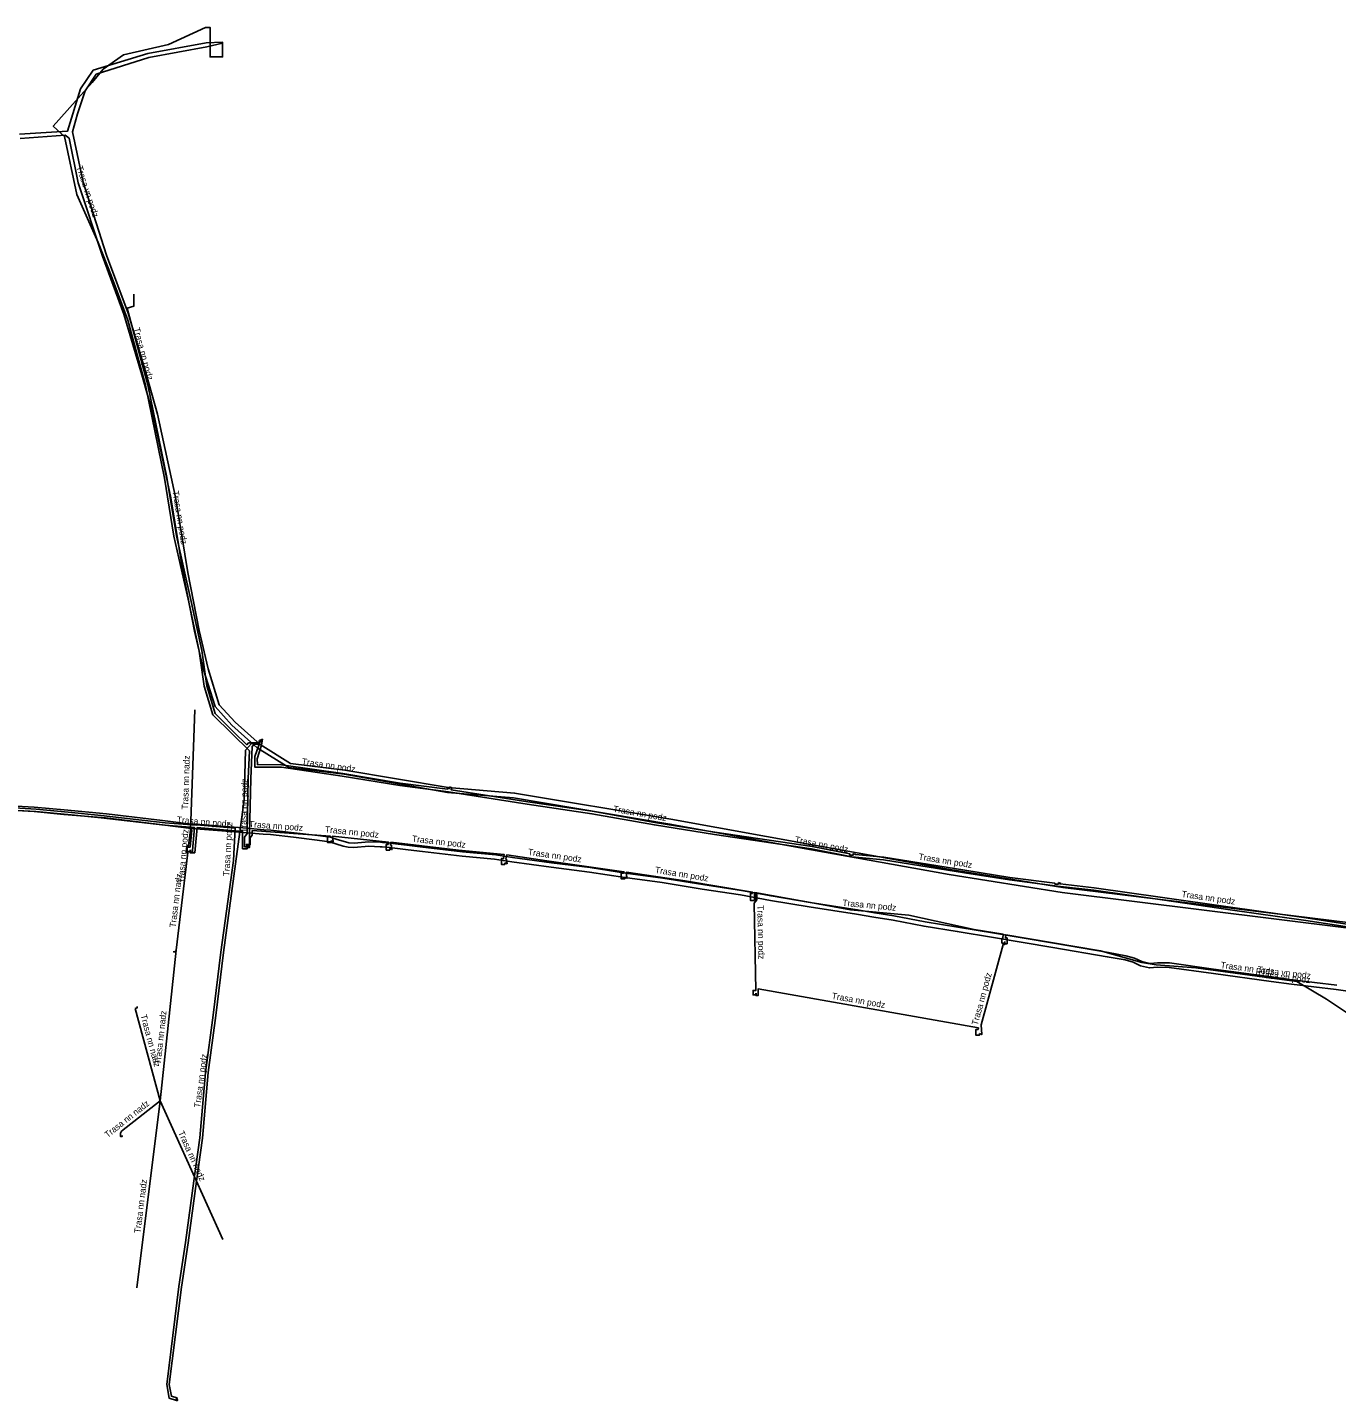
# Model space of a CAD drawing. Extents: x -704292 to -701313, y -1010090 to -1007885.
# Drawn here: x -702533.5 to -702326.6, y -1008863.3 to -1008646.4 of the extents above; entities that cross this region are included whole.
import ezdxf

# ---------------------------------------------------------------- set-up
doc = ezdxf.new("R2010")
doc.units = 0
for name, color, linetype in [('Level 13', 7, 'Continuous'), ('Level 15', 7, 'Continuous'), ('Level 20', 7, 'Continuous'), ('Level 25', 7, 'Continuous')]:
    doc.layers.add(name, color=color, linetype=linetype)

msp = doc.modelspace()

# ---------------------------------------------------------------- linework, layer by layer
at = {"layer": 'Level 13'}
for p, q in [((-702507.7, -1008773.21), (-702507.03, -1008754.23)), ((-702512.5, -1008815.97), (-702509.95, -1008792.21)), ((-702516.42, -1008801.39), (-702512.5, -1008815.97)), ((-702518.59, -1008820.78), (-702512.5, -1008815.97)), ((-702516.2, -1008845.55), (-702512.5, -1008815.97)), ((-702502.61, -1008837.9), (-702512.5, -1008815.97))]:
    msp.add_line(p, q, dxfattribs=at)
for points in [[(-702507.7, -1008773.21), (-702507.99, -1008775.67), (-702508.28, -1008775.71), (-702508.38, -1008776.75), (-702508.12, -1008776.76), (-702509.95, -1008792.21)], [(-702510.35, -1008792.35), (-702510.35, -1008792.46), (-702510.2, -1008792.46), (-702509.95, -1008792.21)], [(-702516.1, -1008801.09), (-702516.1, -1008801.29), (-702516.42, -1008801.39)], [(-702518.51, -1008821.47), (-702518.51, -1008821.64), (-702518.74, -1008821.64), (-702518.74, -1008821.11), (-702518.59, -1008820.78)]]:
    msp.add_lwpolyline(points, dxfattribs=at)
at = {"layer": 'Level 15'}
for points in [[(-702502.62, -1008648.89), (-702502.63, -1008651.08), (-702504.61, -1008651.08), (-702504.61, -1008646.43), (-702505.3, -1008646.44), (-702511.19, -1008649.13), (-702518.26, -1008650.73), (-702521.47, -1008653.04), (-702523.24, -1008655.1), (-702529.38, -1008662), (-702527.58, -1008663.66), (-702525.65, -1008672.8), (-702522.29, -1008680.39), (-702520.21, -1008685.61), (-702517.6, -1008692.67), (-702516.17, -1008697.91), (-702514.83, -1008702.96), (-702511.81, -1008717.61), (-702510.31, -1008726.81), (-702507.97, -1008737.19), (-702506.33, -1008744.93), (-702505.52, -1008750.49), (-702504.14, -1008755.01), (-702501.12, -1008758.01), (-702498.37, -1008760.72), (-702498.57, -1008765.08), (-702498.75, -1008773.77), (-702499.16, -1008774.32), (-702499.16, -1008775.86), (-702498.65, -1008775.86), (-702498.65, -1008775.66)], [(-702496.79, -1008759.05), (-702496.79, -1008759.45), (-702498.53, -1008759.45), (-702498.8, -1008759.74), (-702500.84, -1008757.73), (-702503.78, -1008754.79), (-702505.12, -1008750.41), (-702505.93, -1008744.85), (-702507.58, -1008737.11), (-702509.91, -1008726.73), (-702511.41, -1008717.53), (-702514.44, -1008702.86), (-702515.79, -1008697.81), (-702517.69, -1008690.79), (-702517.2, -1008690.63), (-702516.63, -1008690.44), (-702516.63, -1008688.55)], [(-702496.82, -1008759.05), (-702496.82, -1008759.55), (-702498.06, -1008759.55), (-702498.98, -1008760.59), (-702499.2, -1008768.46), (-702502.5, -1008792.58), (-702503.71, -1008802.52), (-702504.92, -1008811.53), (-702505.81, -1008821.88), (-702506.77, -1008828.66), (-702508.06, -1008838.41), (-702509.12, -1008845.4), (-702511.06, -1008860.78), (-702510.7, -1008862.65), (-702509.85, -1008862.91), (-702509.8, -1008863.07), (-702509.94, -1008863.07), (-702509.94, -1008863.33), (-702509.79, -1008863.33), (-702509.79, -1008863.19)], [(-702498.7, -1008775.66), (-702498.7, -1008775.96), (-702498.35, -1008775.96), (-702498.35, -1008773.75), (-702498.17, -1008765.1), (-702497.94, -1008759.99), (-702497.63, -1008759.65), (-702496.84, -1008759.65), (-702496.84, -1008759.05)], [(-702319.76, -1008789.31), (-702331.48, -1008787.48), (-702343.45, -1008785.8), (-702354.18, -1008784.26), (-702364.96, -1008782.73), (-702370.7, -1008782.08), (-702378.28, -1008781.1), (-702385.41, -1008779.96), (-702398.19, -1008777.9), (-702403.2, -1008777.43), (-702409.56, -1008776.2), (-702424.93, -1008773.93), (-702434.39, -1008772.4), (-702444.27, -1008770.65), (-702454.48, -1008769.15), (-702466.95, -1008767.2), (-702474.61, -1008766.2), (-702483.71, -1008764.69), (-702493.33, -1008763.3), (-702497.55, -1008763.27), (-702497.51, -1008761.6), (-702496.67, -1008759.25), (-702496.57, -1008759.25), (-702496.57, -1008759.08), (-702496.66, -1008759.01), (-702496.77, -1008758.98)], [(-702466.77, -1008766.37), (-702466.77, -1008766.63), (-702467.1, -1008766.63), (-702467.11, -1008766.77), (-702474.55, -1008765.8), (-702483.65, -1008764.29), (-702493.3, -1008762.9), (-702497.12, -1008762.87), (-702497.16, -1008761.96), (-702496.47, -1008759.83), (-702496.34, -1008758.88), (-702496.63, -1008759.04), (-702496.79, -1008758.98)], [(-702507.73, -1008776.34), (-702507.73, -1008776.71), (-702507.39, -1008776.71), (-702507.39, -1008776.44), (-702507.06, -1008772.82), (-702511.76, -1008772.45), (-702521.83, -1008771.29), (-702527.06, -1008770.78), (-702532.12, -1008770.3), (-702540.73, -1008769.79), (-702546.04, -1008769.42), (-702550.78, -1008769.18), (-702555.11, -1008768.84), (-702558.87, -1008768.34), (-702563, -1008767.7), (-702567.32, -1008767.51), (-702571.85, -1008767.18), (-702574.96, -1008766.8), (-702575.12, -1008767.62), (-702574.91, -1008767.62), (-702574.81, -1008768.33), (-702575.16, -1008768.17)], [(-702402.98, -1008776.91), (-702402.98, -1008777.17), (-702403.53, -1008777.17), (-702403.53, -1008776.96), (-702409.5, -1008775.8), (-702424.87, -1008773.53), (-702434.33, -1008772), (-702444.21, -1008770.25), (-702454.42, -1008768.75), (-702466.52, -1008766.86), (-702466.42, -1008766.53), (-702466.77, -1008766.37)], [(-702509.77, -1008863.19), (-702509.77, -1008863.31), (-702509.9, -1008863.31), (-702511.04, -1008862.96), (-702511.46, -1008860.8), (-702509.52, -1008845.34), (-702508.46, -1008838.35), (-702507.17, -1008828.6), (-702506.21, -1008821.84), (-702505.32, -1008811.49), (-702504.11, -1008802.46), (-702502.9, -1008792.52), (-702500.92, -1008778.02), (-702500.62, -1008772.89), (-702506.75, -1008772.41), (-702506.76, -1008772.44), (-702511.72, -1008772.05), (-702521.79, -1008770.89), (-702527.02, -1008770.38), (-702532.09, -1008769.9), (-702540.71, -1008769.39)], [(-702507.71, -1008776.34), (-702507.71, -1008776.61), (-702508.2, -1008776.61), (-702508.2, -1008775.9), (-702507.75, -1008775.9), (-702507.5, -1008773.21), (-702507.7, -1008773.21)], [(-702507.76, -1008776.34), (-702507.76, -1008776.81), (-702507.03, -1008776.81), (-702506.66, -1008772.82), (-702499.46, -1008773.44), (-702499.46, -1008776.17), (-702498.73, -1008776.17), (-702498.73, -1008775.66)], [(-702498.73, -1008775.59), (-702498.85, -1008775.63), (-702498.85, -1008775.48), (-702498.57, -1008775.48), (-702498.25, -1008775.51), (-702498.25, -1008774.44), (-702497.96, -1008774.04), (-702497.94, -1008773.29), (-702485.6, -1008774.18), (-702485.64, -1008774.27), (-702486.07, -1008774.27), (-702486.07, -1008775.18), (-702485.52, -1008775.18), (-702485.52, -1008774.92)], [(-702485.52, -1008774.92), (-702485.17, -1008775.08), (-702485.27, -1008774.2), (-702476.43, -1008775.11), (-702476.47, -1008775.48), (-702476.77, -1008775.48), (-702476.77, -1008776.39), (-702476.22, -1008776.39), (-702476.22, -1008776.13)], [(-702476.22, -1008776.13), (-702475.87, -1008776.29), (-702475.96, -1008775.58), (-702476.08, -1008775.58), (-702476.03, -1008775.15), (-702465.34, -1008776.41), (-702458.13, -1008777.08), (-702458.24, -1008777.73), (-702458.57, -1008777.73), (-702458.57, -1008778.64), (-702458.02, -1008778.64), (-702458.02, -1008778.38)], [(-702458.02, -1008778.38), (-702457.67, -1008778.54), (-702457.77, -1008777.83), (-702457.85, -1008777.83), (-702457.73, -1008777.13), (-702451.39, -1008778.07), (-702439.21, -1008779.81), (-702439.27, -1008780.01), (-702439.64, -1008780.01), (-702439.64, -1008780.92), (-702439.09, -1008780.92), (-702439.09, -1008780.66)], [(-702370.56, -1008781.5), (-702370.56, -1008781.76), (-702371.11, -1008781.76), (-702371.11, -1008781.62), (-702378.22, -1008780.7), (-702385.35, -1008779.56), (-702398.14, -1008777.5), (-702402.63, -1008777.07), (-702402.98, -1008776.91)], [(-702439.09, -1008780.66), (-702438.74, -1008780.82), (-702438.83, -1008780.11), (-702438.88, -1008780.11), (-702438.81, -1008779.87), (-702429.55, -1008781.26), (-702418.92, -1008783.02), (-702418.91, -1008783.22), (-702419.24, -1008783.22), (-702419.24, -1008784.33), (-702418.59, -1008784.33), (-702418.59, -1008783.97)], [(-702319.56, -1008788.57), (-702319.56, -1008788.83), (-702319.9, -1008788.83), (-702319.91, -1008788.88), (-702331.42, -1008787.08), (-702343.39, -1008785.4), (-702354.12, -1008783.86), (-702364.92, -1008782.33), (-702370.3, -1008781.73), (-702370.21, -1008781.66), (-702370.56, -1008781.5)], [(-702418.59, -1008783.86), (-702418.59, -1008783.32), (-702418.23, -1008783.32), (-702418.23, -1008784.23), (-702418.66, -1008784.78), (-702418.35, -1008798.54), (-702418.81, -1008798.54), (-702418.81, -1008799.25), (-702418.31, -1008799.25), (-702418.31, -1008798.98)], [(-702418.59, -1008783.97), (-702418.33, -1008784.16), (-702418.33, -1008783.42), (-702418.5, -1008783.42), (-702418.52, -1008783.09), (-702408.57, -1008784.89), (-702403.41, -1008785.8), (-702394.19, -1008786.68), (-702383.89, -1008788.91), (-702379.28, -1008789.68), (-702379.34, -1008790.36), (-702379.5, -1008790.36), (-702379.5, -1008791.07), (-702379.04, -1008791.07), (-702379.04, -1008790.8)], [(-702383.04, -1008805.37), (-702382.69, -1008805.53), (-702382.79, -1008803.99), (-702379.3, -1008791.27), (-702379.02, -1008791.27), (-702379.02, -1008790.8)], [(-702314.19, -1008812.88), (-702315.88, -1008818.28), (-702316.13, -1008818.54), (-702318.33, -1008817.99), (-702319.09, -1008816.79), (-702318.78, -1008807.55), (-702318.87, -1008806.1), (-702321.26, -1008804.56), (-702328.21, -1008799.91), (-702332.91, -1008797.14), (-702337.2, -1008796.54), (-702348.84, -1008794.98), (-702355.12, -1008794.5), (-702357.38, -1008794.12), (-702363.94, -1008792.3), (-702378.88, -1008789.74), (-702378.92, -1008790.26), (-702378.69, -1008790.26), (-702378.69, -1008791.17), (-702379.04, -1008791.17), (-702379.04, -1008790.8)], [(-702383.04, -1008805.37), (-702383.04, -1008805.63), (-702383.59, -1008805.63), (-702383.59, -1008804.72), (-702383.26, -1008804.72), (-702383.21, -1008804.48), (-702418.01, -1008798.32), (-702418.01, -1008799.35), (-702418.36, -1008799.35), (-702418.36, -1008798.98)]]:
    msp.add_lwpolyline(points, dxfattribs=at)
at = {"layer": 'Level 25'}
for points in [[(-702502.64, -1008648.8), (-702502.64, -1008648.74), (-702505.24, -1008648.86), (-702514.44, -1008650.56), (-702523.07, -1008653.18), (-702525.09, -1008656.13), (-702527.12, -1008662.8), (-702534.71, -1008663.31)], [(-702309, -1008789.77), (-702369.85, -1008782.28), (-702387.67, -1008779.42), (-702409.42, -1008775.53), (-702431.79, -1008771.5), (-702456.5, -1008767.38), (-702467, -1008766.49), (-702483.31, -1008763.73), (-702491.89, -1008762.71), (-702496.71, -1008759.68), (-702500.65, -1008756.17), (-702503.16, -1008753.41), (-702504.91, -1008747.76), (-702506.33, -1008741.71), (-702508.13, -1008732.51), (-702510.07, -1008720.64), (-702512.91, -1008707.51), (-702514.69, -1008701.13), (-702517.56, -1008691.56), (-702520.96, -1008682.4), (-702524.67, -1008670.85), (-702526.32, -1008662.93), (-702525.55, -1008660.05), (-702524.36, -1008656.43), (-702522.58, -1008653.82), (-702514.27, -1008651.18), (-702505.11, -1008649.48), (-702502.64, -1008648.93), (-702502.64, -1008648.86)], [(-702534.63, -1008663.99), (-702527.49, -1008663.44), (-702526.89, -1008663.92), (-702525.43, -1008671), (-702521.62, -1008682.58), (-702518.23, -1008691.73), (-702515.36, -1008701.28), (-702513.6, -1008707.63), (-702510.78, -1008720.73), (-702508.84, -1008732.59), (-702507.04, -1008741.82), (-702505.62, -1008747.9), (-702503.81, -1008753.72), (-702501.18, -1008756.62), (-702497.17, -1008760.2), (-702492.16, -1008763.35), (-702483.44, -1008764.4), (-702467.08, -1008767.26), (-702456.64, -1008768.15), (-702431.96, -1008772.28), (-702409.6, -1008776.32), (-702387.84, -1008780.22), (-702370, -1008783.09), (-702313.69, -1008790.08)], [(-702496.1, -1008773.16), (-702498.72, -1008772.92), (-702506.9, -1008772.3), (-702507.53, -1008772.26), (-702512.1, -1008771.69), (-702520.94, -1008770.63), (-702527.65, -1008770.03), (-702532.39, -1008769.58), (-702539.91, -1008769.16)], [(-702496.19, -1008773.85), (-702498.7, -1008773.63), (-702506.85, -1008773.02), (-702507.57, -1008772.97), (-702512.13, -1008772.39), (-702521.14, -1008771.31), (-702527.7, -1008770.74), (-702532.4, -1008770.28), (-702539.92, -1008769.86)], [(-702321.88, -1008799.11), (-702326.66, -1008798.4), (-702333.74, -1008797.58), (-702336.95, -1008797.12), (-702346.04, -1008795.9), (-702353.08, -1008794.9), (-702354.93, -1008794.88), (-702356.18, -1008794.98), (-702357.61, -1008794.66), (-702358.76, -1008794.09), (-702360.03, -1008793.74), (-702362.85, -1008793.24), (-702371.46, -1008791.75), (-702380.82, -1008790.2), (-702386.55, -1008789.23), (-702391.8, -1008788.42), (-702396.7, -1008787.46), (-702399.72, -1008787), (-702402.49, -1008786.51), (-702409.95, -1008785.33), (-702416.06, -1008784.34), (-702420.81, -1008783.46), (-702426.88, -1008782.53), (-702433.18, -1008781.51), (-702439.08, -1008780.71), (-702444.68, -1008779.85), (-702450.69, -1008779.07), (-702456.93, -1008778.24), (-702459.64, -1008777.83), (-702464.78, -1008777.36), (-702471.05, -1008776.61), (-702473.33, -1008776.32), (-702475.39, -1008776.07), (-702476.24, -1008775.97), (-702477.42, -1008775.86), (-702477.73, -1008775.84), (-702479.51, -1008775.77), (-702481.9, -1008775.98), (-702482.77, -1008775.94), (-702483.56, -1008775.74), (-702485.71, -1008775.05), (-702487.67, -1008774.79), (-702491.43, -1008774.35), (-702495.06, -1008773.94), (-702496.19, -1008773.85)], [(-702326.56, -1008797.71), (-702333.65, -1008796.88), (-702336.89, -1008796.41), (-702346.06, -1008795.19), (-702353.02, -1008794.21), (-702354.9, -1008794.19), (-702356.14, -1008794.29), (-702357.39, -1008794), (-702358.53, -1008793.43), (-702359.9, -1008793.06), (-702362.68, -1008792.56), (-702371.27, -1008791.06), (-702380.66, -1008789.51), (-702386.47, -1008788.54), (-702391.61, -1008787.73), (-702396.56, -1008786.78), (-702399.58, -1008786.3), (-702402.36, -1008785.81), (-702409.8, -1008784.65), (-702415.97, -1008783.63), (-702420.66, -1008782.78), (-702426.73, -1008781.84), (-702433.07, -1008780.81), (-702438.95, -1008780.01), (-702444.56, -1008779.15), (-702450.64, -1008778.37), (-702456.84, -1008777.53), (-702459.45, -1008777.15), (-702464.7, -1008776.67), (-702470.97, -1008775.93), (-702473.11, -1008775.64), (-702475.32, -1008775.37), (-702476.15, -1008775.27), (-702477.35, -1008775.16), (-702477.66, -1008775.14), (-702479.5, -1008775.06), (-702481.83, -1008775.26), (-702482.67, -1008775.23), (-702484.7, -1008774.63), (-702485.59, -1008774.36), (-702487.59, -1008774.1), (-702491.33, -1008773.65), (-702494.98, -1008773.25), (-702496.1, -1008773.16)]]:
    msp.add_lwpolyline(points, dxfattribs=at)

# ---------------------------------------------------------------- texts
at = {"layer": 'Level 20'}
for s, rotation, p in [('Trasa vn podz', 288.2343, (-702525.74, -1008668.47)), ('Trasa nn podz', 284.9672, (-702516.71, -1008693.98)), ('Trasa nn podz', 279.26, (-702510.55, -1008719.7)), ('Trasa nn nadz', 87.9658, (-702508.09, -1008769.99)), ('Trasa nn podz', 351.7863, (-702490.16, -1008762.85)), ('Trasa nn podz', 88.8065, (-702498.85, -1008773.65)), ('Trasa nn podz', 349.9557, (-702440.98, -1008770.32)), ('Trasa nn podz', 355.1128, (-702509.9, -1008772.04)), ('Trasa nn podz', 355.9053, (-702498.48, -1008772.75)), ('Trasa nn podz', 84.8045, (-702508.77, -1008781.63)), ('Trasa nn podz', 86.7464, (-702501.56, -1008780.54)), ('Trasa nn podz', 354.1411, (-702486.49, -1008773.57)), ('Trasa nn podz', 353.2964, (-702472.75, -1008775.04)), ('Trasa nn podz', 351.8633, (-702454.43, -1008777.13)), ('Trasa nn podz', 349.0545, (-702412.27, -1008775.16)), ('Trasa nn podz', 350.8434, (-702392.72, -1008777.87)), ('Trasa nn nadz', 83.2554, (-702510.03, -1008788.66)), ('Trasa nn podz', 350.6149, (-702434.36, -1008779.96)), ('Trasa nn podz', 354.5479, (-702404.73, -1008785.17)), ('Trasa nn podz', 351.8324, (-702351.16, -1008783.78)), ('Trasa nn podz', 271.2511, (-702418.15, -1008785.09)), ('Trasa nn podz', 352.3667, (-702344.99, -1008794.99)), ('Trasa vn podz', 353.4024, (-702339.25, -1008796.44)), ('Trasa vn podz', 353.2681, (-702339.16, -1008795.72)), ('Trasa nn podz', 74.6649, (-702383.34, -1008804.13)), ('Trasa nn podz', 349.9564, (-702406.44, -1008799.86)), ('Trasa nn nadz', 83.8769, (-702512.39, -1008810.29)), ('Trasa nn nadz', 285.0634, (-702515.61, -1008802.48)), ('Trasa nn podz', 82.3598, (-702506.17, -1008817.12)), ('Trasa nn nadz', 38.2838, (-702520.79, -1008821.88)), ('Trasa nn nadz', 294.2825, (-702509.68, -1008821)), ('Trasa nn nadz', 82.8781, (-702515.62, -1008836.94))]:
    msp.add_text(s, height=1, rotation=rotation, dxfattribs=at).set_placement(p)

doc.saveas('drawing.dxf')
